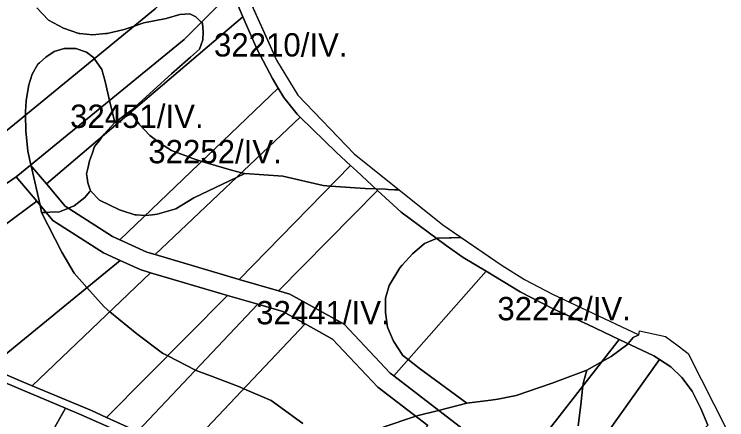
# Model space of a CAD drawing. Extents: x -522079 to -518792, y -1142400 to -1139961.
# Drawn here: x -520002.4 to -519544.3, y -1140912.1 to -1140651.2 of the extents above; entities that cross this region are included whole.
import ezdxf

# ---------------------------------------------------------------- set-up
doc = ezdxf.new("R2010")
doc.units = 0
for name, color, linetype in [('Hranice parcel', 7, 'Continuous'), ('Parcelní čísla', 7, 'Continuous'), ('Poz předměty', 7, 'Continuous'), ('Značky bodu BP', 7, 'Continuous')]:
    doc.layers.add(name, color=color, linetype=linetype)

msp = doc.modelspace()

# ---------------------------------------------------------------- linework, layer by layer
at = {"layer": 'Hranice parcel'}
for points in [[(-519855.18, -1140633.03), (-519833.7, -1140680.7), (-519820.17, -1140703.4), (-519783.91, -1140740.96), (-519726.89, -1140786.75), (-519688.67, -1140812.79), (-519674.4, -1140821.79), (-519656.36, -1140831.22), (-519600.86, -1140857.49), (-519600.42, -1140854.95), (-519583.72, -1140858.5), (-519575.54, -1140864.6), (-519569.14, -1140869.38), (-519544.31, -1140918.54)], [(-519556.41, -1140915.6), (-519561.03, -1140904.86), (-519566.48, -1140893.71), (-519573.15, -1140884.93), (-519580.34, -1140878), (-519587.52, -1140873.31), (-519591.11, -1140871.05), (-519613.39, -1140860.38), (-519633.63, -1140850.83), (-519655.55, -1140840.89), (-519677.02, -1140829.78), (-519698.98, -1140816.54), (-519713.71, -1140807.66), (-519724.7, -1140800.07), (-519753.73, -1140778.67), (-519768.84, -1140764.57), (-519782.42, -1140752.04), (-519786.12, -1140748.61), (-519795.23, -1140740.19), (-519818.61, -1140717.36), (-519820.55, -1140715.47), (-519829.11, -1140704.83), (-519832.73, -1140698.73), (-519836.32, -1140692.64), (-519846.13, -1140673.83), (-519855.49, -1140652.85), (-519862.3, -1140636.3)], [(-519736.43, -1140915.9), (-519768.72, -1140891.13), (-519797.7, -1140860.26), (-519815.37, -1140850.5), (-519829.78, -1140842.53), (-519845.71, -1140837.84), (-519865.19, -1140832.11), (-519914.69, -1140817.53), (-519921.41, -1140815.55), (-519934.39, -1140809.6), (-519944.96, -1140804.75), (-519977.56, -1140783.82), (-519987.93, -1140771.54), (-520001.24, -1140755.77), (-519991.87, -1140748.27), (-519981.63, -1140760.4), (-519969.55, -1140774.7), (-519939.19, -1140794.19), (-519934.47, -1140796.36), (-519917.19, -1140804.28), (-519911.71, -1140805.9), (-519857.7, -1140821.8), (-519832.56, -1140829.21), (-519825.13, -1140831.39), (-519790.25, -1140850.67), (-519760.64, -1140882.2), (-519758.42, -1140883.91), (-519697.68, -1140930.5)], [(-520018.57, -1140878.52), (-519997.49, -1140887.4), (-519990.79, -1140890.22), (-519952.82, -1140906.1), (-519943.08, -1140910.55), (-519923.13, -1140919.66)], [(-519927.83, -1140922.94), (-519959.29, -1140908.89), (-519969.45, -1140904.62), (-519999.48, -1140892), (-520022.73, -1140882.19)]]:
    msp.add_lwpolyline(points, dxfattribs=at)
at = {"layer": 'Parcelní čísla'}
for points in [[(-519911.88, -1140647.84), (-520013.2, -1140730.8), (-520072.01, -1140664.71), (-520082.56, -1140649.64), (-519886.24, -1140527.38), (-519882.2, -1140547.1), (-519878.23, -1140567.62), (-519875.11, -1140585.42), (-519873.69, -1140593.69), (-519873.07, -1140596.47), (-519870.83, -1140606.54)], [(-519862.3, -1140636.3), (-519855.49, -1140652.85), (-519981.63, -1140760.4), (-519991.87, -1140748.27), (-519893.23, -1140667.47)], [(-519981.63, -1140760.4), (-519855.49, -1140652.85), (-519846.13, -1140673.83), (-519836.32, -1140692.64), (-519832.73, -1140698.73), (-519934.47, -1140796.36), (-519939.19, -1140794.19), (-519969.55, -1140774.7)], [(-519832.73, -1140698.73), (-519829.11, -1140704.83), (-519820.55, -1140715.47), (-519818.61, -1140717.36), (-519911.71, -1140805.9), (-519917.19, -1140804.28), (-519934.47, -1140796.36)], [(-519911.71, -1140805.9), (-519818.61, -1140717.36), (-519795.23, -1140740.19), (-519786.12, -1140748.61), (-519857.7, -1140821.8)], [(-519857.7, -1140821.8), (-519786.12, -1140748.61), (-519782.42, -1140752.04), (-519768.84, -1140764.57), (-519832.56, -1140829.21)], [(-520001.24, -1140755.77), (-519987.93, -1140771.54), (-520091.34, -1140848.28), (-520106.23, -1140841.79), (-520119.77, -1140834.99), (-520068.52, -1140802.68), (-520010.06, -1140762.16)], [(-519698.98, -1140816.54), (-519758.42, -1140883.91), (-519760.64, -1140882.2), (-519790.25, -1140850.67), (-519825.13, -1140831.39), (-519832.56, -1140829.21), (-519768.84, -1140764.57), (-519753.73, -1140778.67), (-519724.7, -1140800.07), (-519713.71, -1140807.66)], [(-520091.34, -1140848.28), (-519987.93, -1140771.54), (-519977.56, -1140783.82), (-519944.96, -1140804.75), (-519934.39, -1140809.6), (-520018.57, -1140878.52), (-520022.3, -1140876.95), (-520034.41, -1140872.06), (-520067.09, -1140858.86)], [(-519934.39, -1140809.6), (-519921.41, -1140815.55), (-519914.69, -1140817.53), (-519990.79, -1140890.22), (-519997.49, -1140887.4), (-520018.57, -1140878.52)], [(-519758.42, -1140883.91), (-519698.98, -1140816.54), (-519677.02, -1140829.78), (-519655.55, -1140840.89), (-519633.63, -1140850.83), (-519613.39, -1140860.38), (-519678.04, -1140943.34), (-519697.68, -1140930.5)], [(-519990.79, -1140890.22), (-519914.69, -1140817.53), (-519865.19, -1140832.11), (-519943.08, -1140910.55), (-519952.82, -1140906.1)], [(-519865.19, -1140832.11), (-519845.71, -1140837.84), (-519923.13, -1140919.66), (-519943.08, -1140910.55)], [(-519923.13, -1140919.66), (-519845.71, -1140837.84), (-519829.78, -1140842.53), (-519815.37, -1140850.5), (-519893.61, -1140933.19), (-519907.29, -1140926.89)], [(-519815.37, -1140850.5), (-519797.7, -1140860.26), (-519768.72, -1140891.13), (-519736.43, -1140915.9), (-519792.75, -1140975.43), (-519809.71, -1140968.63), (-519858.03, -1140948.23), (-519890.83, -1140934.46), (-519893.61, -1140933.19)], [(-519654.13, -1140967.02), (-519587.52, -1140873.31), (-519580.34, -1140878), (-519573.15, -1140884.93), (-519566.48, -1140893.71), (-519561.03, -1140904.86), (-519556.41, -1140915.6), (-519632.87, -1140997.67), (-519645.74, -1140981.03)]]:
    msp.add_lwpolyline(points, close=True, dxfattribs=at)
at = {"layer": 'Poz předměty'}
for points in [[(-519862.3, -1140636.3), (-519893.23, -1140667.47), (-519991.87, -1140748.27), (-520001.24, -1140755.77), (-520010.06, -1140762.16), (-520068.52, -1140802.68), (-520119.77, -1140834.99), (-520149.6, -1140820.02), (-520083.41, -1140780.15), (-520025.44, -1140739.97), (-520022.9, -1140738.15), (-520013.2, -1140730.8), (-519911.88, -1140647.84), (-519870.83, -1140606.54), (-519868.76, -1140615.85)], [(-519587.52, -1140873.31), (-519654.13, -1140967.02), (-519662.03, -1140953.81), (-519678.04, -1140943.34), (-519613.39, -1140860.38), (-519591.11, -1140871.05)], [(-520022.73, -1140882.19), (-519999.48, -1140892), (-519969.45, -1140904.62), (-520002.28, -1140962.91), (-520009.84, -1140957.29), (-520015.17, -1140949.95), (-520029.76, -1140941.98), (-520046.33, -1140932.29), (-520051.93, -1140931.48), (-520055.67, -1140929.56)], [(-519969.45, -1140904.62), (-519959.29, -1140908.89), (-519927.83, -1140922.94), (-519916.21, -1140928.63), (-519943.51, -1140985.08), (-519947.03, -1140986.05), (-519959.93, -1140985.31), (-519965.47, -1140973.69), (-519974.08, -1140974.02), (-519986.94, -1140971.3), (-519999.3, -1140964.63), (-520002.28, -1140962.91)]]:
    msp.add_lwpolyline(points, close=True, dxfattribs=at)
at = {"layer": 'Značky bodu BP'}
for points in [[(-519855.18, -1140633.03), (-519839.36, -1140668.14), (-519833.7, -1140680.7), (-519820.17, -1140703.4), (-519783.91, -1140740.96), (-519754.92, -1140764.24), (-519757.79, -1140764.12), (-519761.97, -1140763.94), (-519763.7, -1140763.87), (-519769.86, -1140763.63), (-519776.69, -1140763.36), (-519799.05, -1140761.83), (-519803.86, -1140761.5), (-519829.8, -1140755.31), (-519854.23, -1140753.74), (-519856.3, -1140753.2), (-519862.74, -1140751.53), (-519878.13, -1140747.12), (-519881.86, -1140745.87), (-519888.11, -1140743.78), (-519889.68, -1140743.26), (-519901.22, -1140738.85), (-519908.36, -1140734.44), (-519915.23, -1140729.2), (-519922.1, -1140722.03), (-519927.37, -1140714.14), (-519927.8, -1140713.5), (-519927.05, -1140712.94), (-519901.22, -1140689.5), (-519889.13, -1140678.75), (-519883.36, -1140673.79), (-519881.16, -1140667.73), (-519880.88, -1140662.49), (-519881.43, -1140656.97), (-519882.12, -1140656.28), (-519885.55, -1140652.84), (-519889.4, -1140650.91), (-519896, -1140651.46), (-519904.79, -1140653.94), (-519919.08, -1140656.7), (-519925.38, -1140658.9), (-519931.72, -1140661.11), (-519942.72, -1140663.59), (-519943.73, -1140663.68), (-519952.06, -1140664.42), (-519960.12, -1140663.66), (-519960.85, -1140663.59), (-519970.75, -1140660.28), (-519980.36, -1140655.04), (-519987.78, -1140647.05)], [(-519987.78, -1140647.05), (-519980.36, -1140655.04), (-519970.75, -1140660.28), (-519960.85, -1140663.59), (-519960.12, -1140663.66), (-519952.06, -1140664.42), (-519943.73, -1140663.68), (-519942.72, -1140663.59), (-519931.72, -1140661.11), (-519925.38, -1140658.9), (-519919.08, -1140656.7), (-519904.79, -1140653.94), (-519896, -1140651.46), (-519889.4, -1140650.91), (-519885.55, -1140652.84), (-519882.12, -1140656.28), (-519881.43, -1140656.97), (-519880.88, -1140662.49), (-519881.16, -1140667.73), (-519883.36, -1140673.79), (-519889.13, -1140678.75), (-519901.22, -1140689.5), (-519927.05, -1140712.94), (-519927.8, -1140713.5), (-519937.77, -1140720.93), (-519941.07, -1140706.66), (-519942.17, -1140701.91), (-519944.02, -1140694.6), (-519946.01, -1140686.75), (-519950.94, -1140679.82), (-519951.51, -1140679.03), (-519955.91, -1140675.72), (-519962.78, -1140673.24), (-519970.2, -1140673.24), (-519976.79, -1140675.17), (-519982.01, -1140678.75), (-519986.11, -1140682.43), (-519987.24, -1140683.44), (-519990.81, -1140689.78), (-519993.01, -1140696.67), (-519994.38, -1140704.11), (-519994.62, -1140706.96), (-519995.21, -1140713.76), (-519995.16, -1140716.02), (-519994.93, -1140726.17), (-519993.56, -1140739.4), (-519991.62, -1140748.07), (-519991.47, -1140748.74), (-519985.83, -1140774.02), (-519984.76, -1140778.82), (-519971.81, -1140804.24), (-519963.78, -1140817.86), (-519955.69, -1140827.03), (-519944.64, -1140839.54), (-519940.94, -1140842.6), (-519923.65, -1140856.89), (-519906.98, -1140869.27), (-519903.75, -1140870.94), (-519885.8, -1140880.2), (-519885.37, -1140880.43), (-519875.57, -1140884.14), (-519857.58, -1140890.95), (-519854.78, -1140892.15), (-519837.21, -1140899.63), (-519816.83, -1140914.5)], [(-519816.83, -1140914.5), (-519837.21, -1140899.63), (-519854.78, -1140892.15), (-519857.58, -1140890.95), (-519875.57, -1140884.14), (-519885.37, -1140880.43), (-519885.8, -1140880.2), (-519903.75, -1140870.94), (-519906.98, -1140869.27), (-519923.65, -1140856.89), (-519940.94, -1140842.6), (-519944.64, -1140839.54), (-519955.69, -1140827.03), (-519963.78, -1140817.86), (-519971.81, -1140804.24), (-519984.76, -1140778.82), (-519982.44, -1140778.71), (-519981.89, -1140778.69), (-519979.47, -1140778.57), (-519973.22, -1140778.27), (-519967.6, -1140775.95), (-519963.88, -1140774.41), (-519957.01, -1140769.17), (-519954.08, -1140765.56), (-519953.43, -1140764.76), (-519947.66, -1140770.83), (-519934.75, -1140777.17), (-519932.87, -1140777.75), (-519924.85, -1140780.2), (-519924.04, -1140780.27), (-519918.19, -1140780.74), (-519917.98, -1140780.75), (-519913.45, -1140780.25), (-519910.56, -1140779.93), (-519898.47, -1140776.34), (-519886.93, -1140769.45), (-519859.55, -1140756.3), (-519854.23, -1140753.74), (-519829.8, -1140755.31), (-519803.86, -1140761.5), (-519799.05, -1140761.83), (-519776.69, -1140763.36), (-519769.86, -1140763.63), (-519763.7, -1140763.87), (-519761.97, -1140763.94), (-519757.79, -1140764.12), (-519754.92, -1140764.24), (-519726.89, -1140786.75), (-519715.13, -1140794.76), (-519721.58, -1140795.04), (-519721.96, -1140795.05), (-519722.47, -1140795.07), (-519730.43, -1140795.31), (-519730.89, -1140795.51), (-519738.57, -1140798.76), (-519746.4, -1140805.36), (-519752.93, -1140812.67), (-519754.54, -1140814.47), (-519761.43, -1140825.78), (-519763.62, -1140833.95), (-519763.62, -1140843.06), (-519762.37, -1140852.48), (-519758.61, -1140861.59), (-519752.66, -1140870.7), (-519749.14, -1140873.4), (-519742.01, -1140878.86), (-519711.33, -1140901.48), (-519729.55, -1140906.05), (-519742.64, -1140909.34), (-519744.27, -1140909.88), (-519765.19, -1140916.87)], [(-519639.93, -1140915.93), (-519638.05, -1140902.43), (-519637.39, -1140896.31), (-519636.75, -1140890.35), (-519636.49, -1140887.98), (-519634.3, -1140880.12), (-519624.48, -1140874.6), (-519618.64, -1140871.33), (-519607.99, -1140863.48), (-519607.68, -1140863.11), (-519606.59, -1140861.83), (-519604.41, -1140859.25), (-519600.86, -1140857.49), (-519600.68, -1140856.47), (-519600.64, -1140856.22), (-519600.42, -1140854.95), (-519583.72, -1140858.5), (-519575.54, -1140864.6), (-519569.14, -1140869.38), (-519544.31, -1140918.54)], [(-519765.19, -1140916.87), (-519744.27, -1140909.88), (-519742.64, -1140909.34), (-519729.55, -1140906.05), (-519711.33, -1140901.48), (-519699.38, -1140900.02), (-519695.98, -1140899.6), (-519691.59, -1140898.75), (-519679.7, -1140896.45), (-519656.53, -1140888.6), (-519634.3, -1140880.12), (-519636.49, -1140887.98), (-519636.75, -1140890.35), (-519637.39, -1140896.31), (-519638.05, -1140902.43), (-519639.93, -1140915.93)]]:
    msp.add_lwpolyline(points, dxfattribs=at)
for points in [[(-519982.44, -1140778.71), (-519984.76, -1140778.82), (-519985.83, -1140774.02), (-519991.47, -1140748.74), (-519991.62, -1140748.07), (-519993.56, -1140739.4), (-519994.93, -1140726.17), (-519995.16, -1140716.02), (-519995.21, -1140713.76), (-519994.62, -1140706.96), (-519994.38, -1140704.11), (-519993.01, -1140696.67), (-519990.81, -1140689.78), (-519987.24, -1140683.44), (-519986.11, -1140682.43), (-519982.01, -1140678.75), (-519976.79, -1140675.17), (-519970.2, -1140673.24), (-519962.78, -1140673.24), (-519955.91, -1140675.72), (-519951.51, -1140679.03), (-519950.94, -1140679.82), (-519946.01, -1140686.75), (-519944.02, -1140694.6), (-519942.17, -1140701.91), (-519941.07, -1140706.66), (-519937.77, -1140720.93), (-519944.64, -1140728.37), (-519945.67, -1140729.74), (-519946.35, -1140730.63), (-519947.66, -1140732.36), (-519950.69, -1140736.37), (-519952.15, -1140740.42), (-519953.98, -1140745.47), (-519955.11, -1140750.48), (-519955.91, -1140754.01), (-519955.54, -1140756.57), (-519955.08, -1140759.8), (-519953.43, -1140764.76), (-519954.08, -1140765.56), (-519957.01, -1140769.17), (-519963.88, -1140774.41), (-519967.6, -1140775.95), (-519973.22, -1140778.27), (-519979.47, -1140778.57), (-519981.89, -1140778.69)], [(-519913.45, -1140780.25), (-519917.98, -1140780.75), (-519918.19, -1140780.74), (-519924.04, -1140780.27), (-519924.85, -1140780.2), (-519932.87, -1140777.75), (-519934.75, -1140777.17), (-519947.66, -1140770.83), (-519953.43, -1140764.76), (-519955.08, -1140759.8), (-519955.54, -1140756.57), (-519955.91, -1140754.01), (-519955.11, -1140750.48), (-519953.98, -1140745.47), (-519952.15, -1140740.42), (-519950.69, -1140736.37), (-519947.66, -1140732.36), (-519946.35, -1140730.63), (-519945.67, -1140729.74), (-519944.64, -1140728.37), (-519937.77, -1140720.93), (-519927.8, -1140713.5), (-519927.37, -1140714.14), (-519922.1, -1140722.03), (-519915.23, -1140729.2), (-519908.36, -1140734.44), (-519901.22, -1140738.85), (-519889.68, -1140743.26), (-519888.11, -1140743.78), (-519881.86, -1140745.87), (-519878.13, -1140747.12), (-519862.74, -1140751.53), (-519856.3, -1140753.2), (-519854.23, -1140753.74), (-519859.55, -1140756.3), (-519886.93, -1140769.45), (-519898.47, -1140776.34), (-519910.56, -1140779.93)], [(-519600.86, -1140857.49), (-519604.41, -1140859.25), (-519606.59, -1140861.83), (-519607.68, -1140863.11), (-519607.99, -1140863.48), (-519618.64, -1140871.33), (-519624.48, -1140874.6), (-519634.3, -1140880.12), (-519656.53, -1140888.6), (-519679.7, -1140896.45), (-519691.59, -1140898.75), (-519695.98, -1140899.6), (-519699.38, -1140900.02), (-519711.33, -1140901.48), (-519742.01, -1140878.86), (-519749.14, -1140873.4), (-519752.66, -1140870.7), (-519758.61, -1140861.59), (-519762.37, -1140852.48), (-519763.62, -1140843.06), (-519763.62, -1140833.95), (-519761.43, -1140825.78), (-519754.54, -1140814.47), (-519752.93, -1140812.67), (-519746.4, -1140805.36), (-519738.57, -1140798.76), (-519730.89, -1140795.51), (-519730.43, -1140795.31), (-519722.47, -1140795.07), (-519721.96, -1140795.05), (-519721.58, -1140795.04), (-519715.13, -1140794.76), (-519688.67, -1140812.79), (-519674.4, -1140821.79), (-519656.36, -1140831.22)]]:
    msp.add_lwpolyline(points, close=True, dxfattribs=at)

# ---------------------------------------------------------------- texts
for s, rotation, p in [('32210/IV.', 360, (-519873.97, -1140678.43)), ('32451/IV.', 360, (-519966.49, -1140724.37)), ('32252/IV.', 360, (-519916.23, -1140747.12)), ('32441/IV.', 0, (-519846.87, -1140850.71)), ('32242/IV.', 360, (-519691.8, -1140848.12))]:
    msp.add_text(s, height=15, rotation=rotation, dxfattribs=at).set_placement(p)

doc.saveas('drawing.dxf')
